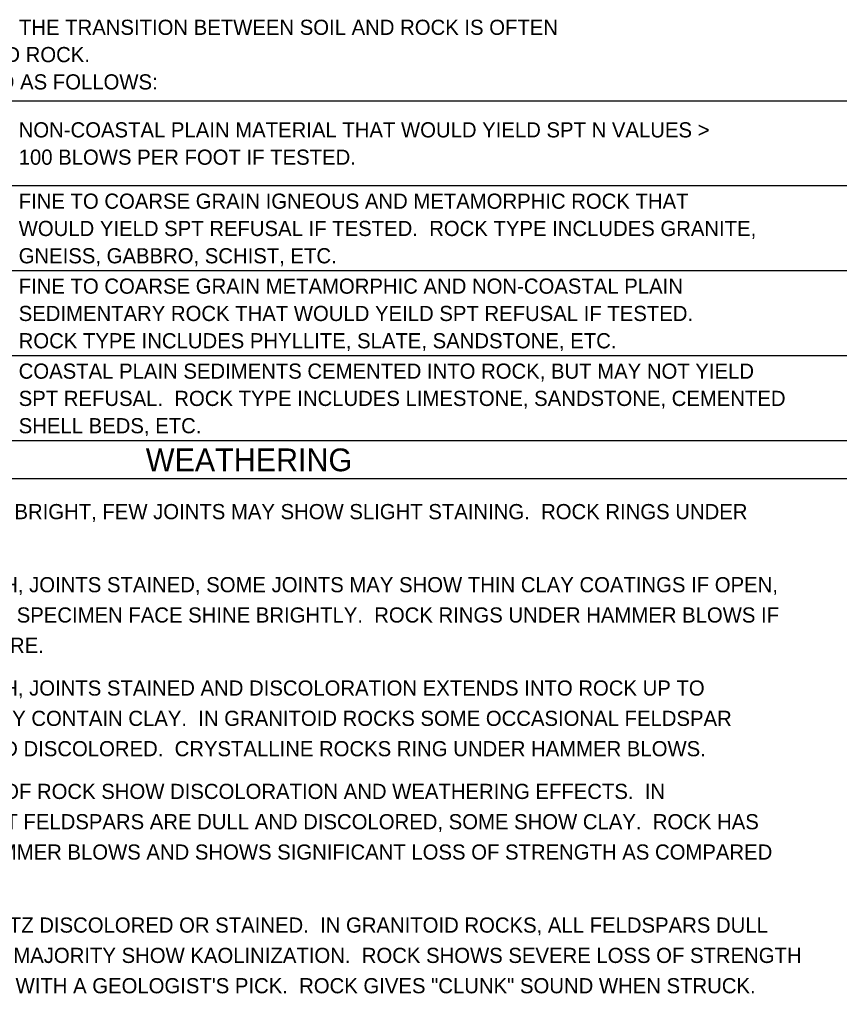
# Model space of a CAD drawing. Extents: x 265553 to 275568, y 168312 to 173522.
# Drawn here: x 267802.5 to 268036.9, y 170736.8 to 171015.3 of the extents above; entities that cross this region are included whole.
import ezdxf

# ---------------------------------------------------------------- set-up
doc = ezdxf.new("R2010")
doc.units = 0
doc.layers.add('Geotech Sheets and Borders Cell', color=7, linetype='Continuous')

msp = doc.modelspace()

# ---------------------------------------------------------------- linework, layer by layer
at = {"layer": 'Geotech Sheets and Borders Cell'}
for p, q in [((268066.96, 170992), (267670.42, 170992)), ((268066.96, 170967.71), (267670.42, 170967.71)), ((268066.96, 170943.42), (267670.42, 170943.42)), ((268066.96, 170919.12), (267670.42, 170919.12)), ((268066.96, 170894.83), (267670.42, 170894.83)), ((268066.96, 170883.98), (267670.42, 170883.98))]:
    msp.add_line(p, q, dxfattribs=at)

# ---------------------------------------------------------------- texts
for s, height, p in [('BLOWS IN NON-COASTAL PLAIN MATERIAL, THE TRANSITION BETWEEN SOIL AND ROCK IS OFTEN', 4.3381, (267678.23, 171010.91)), ('REPRESENTED BY A ZONE OF WEATHERED ROCK.', 4.3381, (267678.23, 171003.11)), ('ROCK MATERIALS ARE TYPICALLY DIVIDED AS FOLLOWS:', 4.3381, (267678.23, 170995.3)), ('NON-COASTAL PLAIN MATERIAL THAT WOULD YIELD SPT N VALUES >', 4.3381, (267802.26, 170981.59)), ('100 BLOWS PER FOOT IF TESTED.', 4.3381, (267802.26, 170973.78)), ('FINE TO COARSE GRAIN IGNEOUS AND METAMORPHIC ROCK THAT ', 4.3381, (267802.26, 170961.2)), ('WOULD YIELD SPT REFUSAL IF TESTED.  ROCK TYPE INCLUDES GRANITE, ', 4.3381, (267802.26, 170953.4)), ('GNEISS, GABBRO, SCHIST, ETC.', 4.3381, (267802.26, 170945.59)), ('FINE TO COARSE GRAIN METAMORPHIC AND NON-COASTAL PLAIN ', 4.3381, (267802.26, 170936.91)), ('SEDIMENTARY ROCK THAT WOULD YEILD SPT REFUSAL IF TESTED.', 4.3381, (267802.26, 170929.1)), ('ROCK TYPE INCLUDES PHYLLITE, SLATE, SANDSTONE, ETC.', 4.3381, (267802.26, 170921.29)), ('COASTAL PLAIN SEDIMENTS CEMENTED INTO ROCK, BUT MAY NOT YIELD ', 4.3381, (267802.26, 170912.61)), ('SPT REFUSAL.  ROCK TYPE INCLUDES LIMESTONE, SANDSTONE, CEMENTED ', 4.3381, (267802.26, 170904.81)), ('SHELL BEDS, ETC.', 4.3381, (267802.26, 170897)), ('WEATHERING', 6.507, (267838.59, 170886.15)), ('ROCK FRESH, CRYSTALS BRIGHT, FEW JOINTS MAY SHOW SLIGHT STAINING.  ROCK RINGS UNDER ', 4.3381, (267727.56, 170872.44)), ('ROCK GENERALLY FRESH, JOINTS STAINED, SOME JOINTS MAY SHOW THIN CLAY COATINGS IF OPEN, ', 4.3381, (267727.56, 170851.55)), ('CRYSTALS ON A BROKEN SPECIMEN FACE SHINE BRIGHTLY.  ROCK RINGS UNDER HAMMER BLOWS IF ', 4.3381, (267727.56, 170842.89)), ('OF A CRYSTALLINE NATURE.', 4.3381, (267727.56, 170834.22)), ('ROCK GENERALLY FRESH, JOINTS STAINED AND DISCOLORATION EXTENDS INTO ROCK UP TO ', 4.3381, (267727.56, 170822)), ('1 INCH.  OPEN JOINTS MAY CONTAIN CLAY.  IN GRANITOID ROCKS SOME OCCASIONAL FELDSPAR ', 4.3381, (267727.56, 170813.33)), ('CRYSTALS ARE DULL AND DISCOLORED.  CRYSTALLINE ROCKS RING UNDER HAMMER BLOWS.', 4.3381, (267727.56, 170804.66)), ('SIGNIFICANT PORTIONS OF ROCK SHOW DISCOLORATION AND WEATHERING EFFECTS.  IN ', 4.3381, (267727.56, 170792.45)), ('GRANITOID ROCKS, MOST FELDSPARS ARE DULL AND DISCOLORED, SOME SHOW CLAY.  ROCK HAS ', 4.3381, (267727.56, 170783.78)), ('DULL SOUND UNDER HAMMER BLOWS AND SHOWS SIGNIFICANT LOSS OF STRENGTH AS COMPARED ', 4.3381, (267727.56, 170775.11)), ('ALL ROCK EXCEPT QUARTZ DISCOLORED OR STAINED.  IN GRANITOID ROCKS, ALL FELDSPARS DULL ', 4.3381, (267727.56, 170754.23)), ('AND DISCOLORED AND A MAJORITY SHOW KAOLINIZATION.  ROCK SHOWS SEVERE LOSS OF STRENGTH', 4.3381, (267727.56, 170745.56)), ('AND CAN BE EXCAVATED WITH A GEOLOGIST\'S PICK.  ROCK GIVES "CLUNK" SOUND WHEN STRUCK.', 4.3381, (267727.56, 170736.89))]:
    msp.add_text(s, height=height, dxfattribs=at).set_placement(p)

doc.saveas('drawing.dxf')
